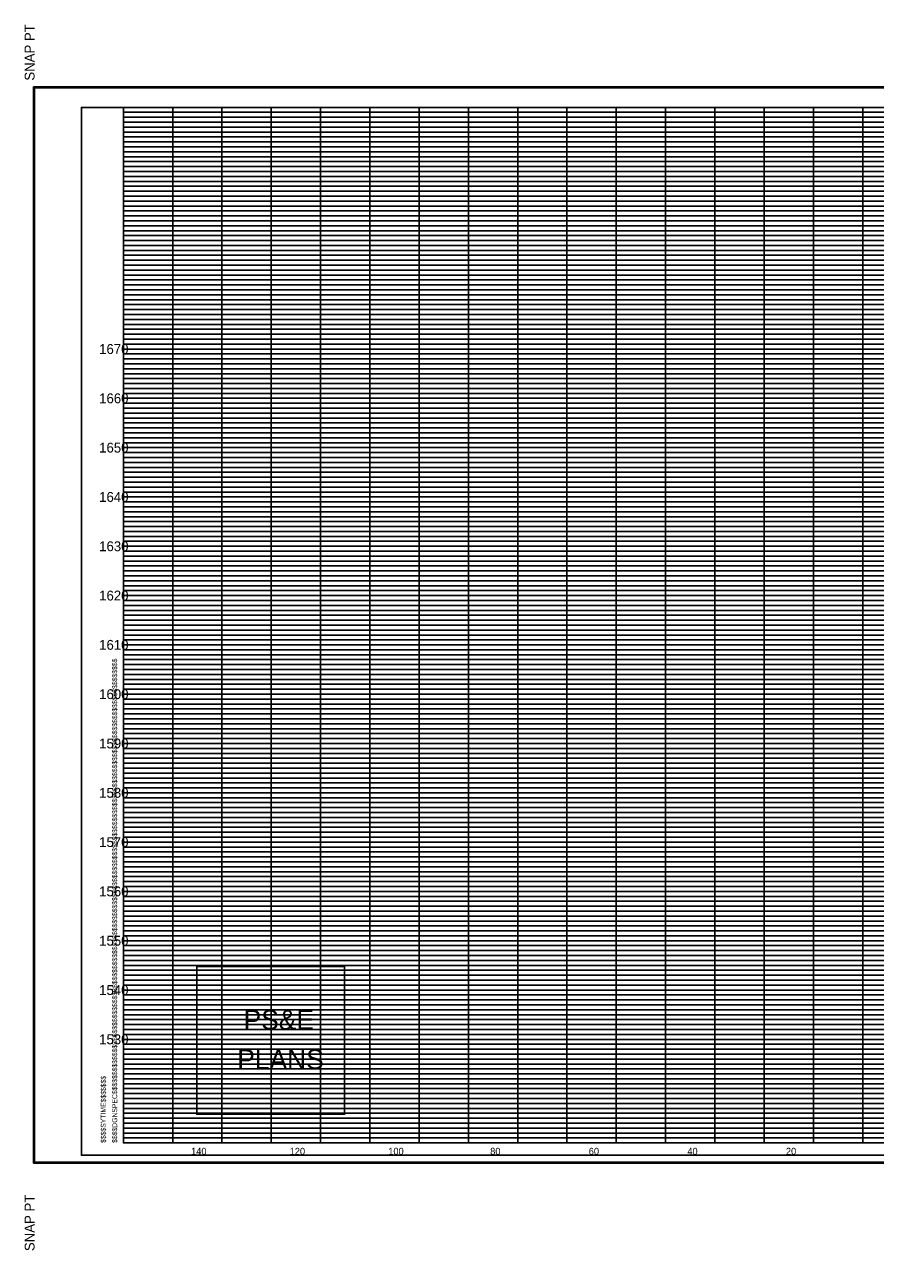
# Model space of a CAD drawing. Extents: x 980 to 1380, y 1248 to 3387.
# Drawn here: x 979.9 to 1152.6, y 2328.2 to 2576.8 of the extents above; entities that cross this region are included whole.
import ezdxf

# ---------------------------------------------------------------- set-up
doc = ezdxf.new("R2010")
doc.units = 0
for name, color, linetype in [('DESIGN - SHEET - Corner Text', 7, 'Continuous'), ('DESIGN - SHEET - Light Grid', 7, 'Continuous'), ('DESIGN - SHEET - Linework', 7, 'Continuous'), ('DESIGN - SHEET - Plot Shape', 7, 'Continuous'), ('DESIGN - TYPICAL - Text', 7, 'Continuous')]:
    doc.layers.add(name, color=color, linetype=linetype)

# ---------------------------------------------------------------- blocks, each defined once
blk = doc.blocks.new('XSTSHT')
at = {"layer": 'DESIGN - SHEET - Light Grid'}
for p, q in [((0, 20.9), (8, 20.9)), ((8, 20.9), (16, 20.9)), ((0, 20.8), (8, 20.8)), ((0, 20.7), (8, 20.7)), ((8, 20.8), (16, 20.8)), ((8, 20.7), (16, 20.7)), ((0, 20.6), (8, 20.6)), ((0, 20.5), (8, 20.5)), ((0, 20.4), (8, 20.4)), ((8, 20.6), (16, 20.6)), ((8, 20.5), (16, 20.5)), ((8, 20.4), (16, 20.4)), ((0, 20.3), (8, 20.3)), ((0, 20.2), (8, 20.2)), ((8, 20.3), (16, 20.3)), ((8, 20.2), (16, 20.2)), ((0, 20.1), (8, 20.1)), ((0, 19.9), (8, 19.9)), ((8, 20.1), (16, 20.1)), ((8, 19.9), (16, 19.9)), ((0, 19.8), (8, 19.8)), ((0, 19.7), (8, 19.7)), ((8, 19.8), (16, 19.8)), ((8, 19.7), (16, 19.7)), ((0, 19.6), (8, 19.6)), ((0, 19.5), (8, 19.5)), ((0, 19.4), (8, 19.4)), ((8, 19.6), (16, 19.6)), ((8, 19.5), (16, 19.5)), ((8, 19.4), (16, 19.4)), ((0, 19.3), (8, 19.3)), ((0, 19.2), (8, 19.2)), ((8, 19.3), (16, 19.3)), ((8, 19.2), (16, 19.2)), ((0, 19.1), (8, 19.1)), ((0, 18.9), (8, 18.9)), ((8, 19.1), (16, 19.1)), ((8, 18.9), (16, 18.9)), ((0, 18.8), (8, 18.8)), ((0, 18.7), (8, 18.7)), ((8, 18.8), (16, 18.8)), ((8, 18.7), (16, 18.7)), ((0, 18.6), (8, 18.6)), ((0, 18.5), (8, 18.5)), ((0, 18.4), (8, 18.4)), ((8, 18.6), (16, 18.6)), ((8, 18.5), (16, 18.5)), ((8, 18.4), (16, 18.4)), ((0, 18.3), (8, 18.3)), ((0, 18.2), (8, 18.2)), ((8, 18.3), (16, 18.3)), ((8, 18.2), (16, 18.2)), ((0, 18.1), (8, 18.1)), ((8, 18.1), (16, 18.1)), ((0, 17.9), (8, 17.9)), ((0, 17.8), (8, 17.8)), ((0, 17.7), (8, 17.7)), ((8, 17.9), (16, 17.9)), ((8, 17.8), (16, 17.8)), ((8, 17.7), (16, 17.7)), ((0, 17.6), (8, 17.6)), ((0, 17.5), (8, 17.5)), ((8, 17.6), (16, 17.6)), ((8, 17.5), (16, 17.5)), ((0, 17.4), (8, 17.4)), ((0, 17.3), (8, 17.3)), ((0, 17.2), (8, 17.2)), ((8, 17.4), (16, 17.4)), ((8, 17.3), (16, 17.3)), ((8, 17.2), (16, 17.2)), ((0, 17.1), (8, 17.1)), ((8, 17.1), (16, 17.1)), ((0, 16.9), (8, 16.9)), ((0, 16.8), (8, 16.8)), ((0, 16.7), (8, 16.7)), ((8, 16.9), (16, 16.9)), ((8, 16.8), (16, 16.8)), ((8, 16.7), (16, 16.7)), ((0, 16.6), (8, 16.6)), ((0, 16.5), (8, 16.5)), ((8, 16.6), (16, 16.6)), ((8, 16.5), (16, 16.5)), ((0, 16.4), (8, 16.4)), ((0, 16.3), (8, 16.3)), ((0, 16.2), (8, 16.2)), ((8, 16.4), (16, 16.4)), ((8, 16.3), (16, 16.3)), ((8, 16.2), (16, 16.2)), ((0, 16.1), (8, 16.1)), ((8, 16.1), (16, 16.1)), ((0, 15.9), (8, 15.9)), ((0, 15.8), (8, 15.8)), ((0, 15.7), (8, 15.7)), ((8, 15.9), (16, 15.9)), ((8, 15.8), (16, 15.8)), ((8, 15.7), (16, 15.7)), ((0, 15.6), (8, 15.6)), ((0, 15.5), (8, 15.5)), ((8, 15.6), (16, 15.6)), ((8, 15.5), (16, 15.5)), ((0, 15.4), (8, 15.4)), ((0, 15.3), (8, 15.3)), ((0, 15.2), (8, 15.2)), ((8, 15.4), (16, 15.4)), ((8, 15.3), (16, 15.3)), ((8, 15.2), (16, 15.2)), ((0, 15.1), (8, 15.1)), ((8, 15.1), (16, 15.1)), ((0, 14.9), (8, 14.9)), ((0, 14.8), (8, 14.8)), ((0, 14.7), (8, 14.7)), ((8, 14.9), (16, 14.9)), ((8, 14.8), (16, 14.8)), ((8, 14.7), (16, 14.7)), ((0, 14.6), (8, 14.6)), ((0, 14.5), (8, 14.5)), ((8, 14.6), (16, 14.6)), ((8, 14.5), (16, 14.5)), ((0, 14.4), (8, 14.4)), ((0, 14.3), (8, 14.3)), ((0, 14.2), (8, 14.2)), ((8, 14.4), (16, 14.4)), ((8, 14.3), (16, 14.3)), ((8, 14.2), (16, 14.2)), ((0, 14.1), (8, 14.1)), ((8, 14.1), (16, 14.1)), ((0, 13.9), (8, 13.9)), ((0, 13.8), (8, 13.8)), ((0, 13.7), (8, 13.7)), ((8, 13.9), (16, 13.9)), ((8, 13.8), (16, 13.8)), ((8, 13.7), (16, 13.7)), ((0, 13.6), (8, 13.6)), ((0, 13.5), (8, 13.5)), ((8, 13.6), (16, 13.6)), ((8, 13.5), (16, 13.5)), ((0, 13.4), (8, 13.4)), ((0, 13.3), (8, 13.3)), ((0, 13.2), (8, 13.2)), ((8, 13.4), (16, 13.4)), ((8, 13.3), (16, 13.3)), ((8, 13.2), (16, 13.2)), ((0, 13.1), (8, 13.1)), ((8, 13.1), (16, 13.1)), ((0, 12.9), (8, 12.9)), ((0, 12.8), (8, 12.8)), ((0, 12.7), (8, 12.7)), ((8, 12.9), (16, 12.9)), ((8, 12.8), (16, 12.8)), ((8, 12.7), (16, 12.7)), ((0, 12.6), (8, 12.6)), ((0, 12.5), (8, 12.5)), ((8, 12.6), (16, 12.6)), ((8, 12.5), (16, 12.5)), ((0, 12.4), (8, 12.4)), ((0, 12.3), (8, 12.3)), ((0, 12.2), (8, 12.2)), ((8, 12.4), (16, 12.4)), ((8, 12.3), (16, 12.3)), ((8, 12.2), (16, 12.2)), ((0, 12.1), (8, 12.1)), ((8, 12.1), (16, 12.1)), ((0, 11.9), (8, 11.9)), ((0, 11.8), (8, 11.8)), ((0, 11.7), (8, 11.7)), ((8, 11.9), (16, 11.9)), ((8, 11.8), (16, 11.8)), ((8, 11.7), (16, 11.7)), ((0, 11.6), (8, 11.6)), ((0, 11.5), (8, 11.5)), ((8, 11.6), (16, 11.6)), ((8, 11.5), (16, 11.5)), ((0, 11.4), (8, 11.4)), ((0, 11.3), (8, 11.3)), ((0, 11.2), (8, 11.2)), ((8, 11.4), (16, 11.4)), ((8, 11.3), (16, 11.3)), ((8, 11.2), (16, 11.2)), ((0, 11.1), (8, 11.1)), ((8, 11.1), (16, 11.1)), ((0, 10.9), (8, 10.9)), ((0, 10.8), (8, 10.8)), ((0, 10.7), (8, 10.7)), ((8, 10.9), (16, 10.9)), ((8, 10.8), (16, 10.8)), ((8, 10.7), (16, 10.7)), ((0, 10.6), (8, 10.6)), ((0, 10.5), (8, 10.5)), ((8, 10.6), (16, 10.6)), ((8, 10.5), (16, 10.5)), ((0, 10.4), (8, 10.4)), ((0, 10.3), (8, 10.3)), ((0, 10.2), (8, 10.2)), ((8, 10.4), (16, 10.4)), ((8, 10.3), (16, 10.3)), ((8, 10.2), (16, 10.2)), ((0, 10.1), (8, 10.1)), ((8, 10.1), (16, 10.1)), ((0, 9.9), (8, 9.9)), ((0, 9.8), (8, 9.8)), ((0, 9.7), (8, 9.7)), ((8, 9.9), (16, 9.9)), ((8, 9.8), (16, 9.8)), ((8, 9.7), (16, 9.7)), ((0, 9.6), (8, 9.6)), ((0, 9.5), (8, 9.5)), ((8, 9.6), (16, 9.6)), ((8, 9.5), (16, 9.5)), ((0, 9.4), (8, 9.4)), ((0, 9.3), (8, 9.3)), ((0, 9.2), (8, 9.2)), ((8, 9.4), (16, 9.4)), ((8, 9.3), (16, 9.3)), ((8, 9.2), (16, 9.2)), ((0, 9.1), (8, 9.1)), ((8, 9.1), (16, 9.1)), ((0, 8.9), (8, 8.9)), ((0, 8.8), (8, 8.8)), ((8, 8.9), (16, 8.9)), ((8, 8.8), (16, 8.8)), ((0, 8.7), (8, 8.7)), ((0, 8.6), (8, 8.6)), ((0, 8.5), (8, 8.5)), ((8, 8.7), (16, 8.7)), ((8, 8.6), (16, 8.6)), ((8, 8.5), (16, 8.5)), ((0, 8.4), (8, 8.4)), ((0, 8.3), (8, 8.3)), ((8, 8.4), (16, 8.4)), ((8, 8.3), (16, 8.3)), ((0, 8.2), (8, 8.2)), ((0, 8.1), (8, 8.1)), ((8, 8.2), (16, 8.2)), ((8, 8.1), (16, 8.1)), ((0, 7.9), (8, 7.9)), ((0, 7.8), (8, 7.8)), ((8, 7.9), (16, 7.9)), ((8, 7.8), (16, 7.8)), ((0, 7.7), (8, 7.7)), ((0, 7.6), (8, 7.6)), ((0, 7.5), (8, 7.5)), ((8, 7.7), (16, 7.7)), ((8, 7.6), (16, 7.6)), ((8, 7.5), (16, 7.5)), ((0, 7.4), (8, 7.4)), ((0, 7.3), (8, 7.3)), ((8, 7.4), (16, 7.4)), ((8, 7.3), (16, 7.3)), ((0, 7.2), (8, 7.2)), ((0, 7.1), (8, 7.1)), ((8, 7.2), (16, 7.2)), ((8, 7.1), (16, 7.1)), ((0, 6.9), (8, 6.9)), ((0, 6.8), (8, 6.8)), ((8, 6.9), (16, 6.9)), ((8, 6.8), (16, 6.8)), ((0, 6.7), (8, 6.7)), ((0, 6.6), (8, 6.6)), ((0, 6.5), (8, 6.5)), ((8, 6.7), (16, 6.7)), ((8, 6.6), (16, 6.6)), ((8, 6.5), (16, 6.5)), ((0, 6.4), (8, 6.4)), ((0, 6.3), (8, 6.3)), ((8, 6.4), (16, 6.4)), ((8, 6.3), (16, 6.3)), ((0, 6.2), (8, 6.2)), ((0, 6.1), (8, 6.1)), ((8, 6.2), (16, 6.2)), ((8, 6.1), (16, 6.1)), ((0, 5.9), (8, 5.9)), ((0, 5.8), (8, 5.8)), ((8, 5.9), (16, 5.9)), ((8, 5.8), (16, 5.8)), ((0, 5.7), (8, 5.7)), ((0, 5.6), (8, 5.6)), ((0, 5.5), (8, 5.5)), ((8, 5.7), (16, 5.7)), ((8, 5.6), (16, 5.6)), ((8, 5.5), (16, 5.5)), ((0, 5.4), (8, 5.4)), ((0, 5.3), (8, 5.3)), ((8, 5.4), (16, 5.4)), ((8, 5.3), (16, 5.3)), ((0, 5.2), (8, 5.2)), ((0, 5.1), (8, 5.1)), ((8, 5.2), (16, 5.2)), ((8, 5.1), (16, 5.1)), ((0, 4.9), (8, 4.9)), ((0, 4.8), (8, 4.8)), ((8, 4.9), (16, 4.9)), ((8, 4.8), (16, 4.8)), ((0, 4.7), (8, 4.7)), ((0, 4.6), (8, 4.6)), ((0, 4.5), (8, 4.5)), ((8, 4.7), (16, 4.7)), ((8, 4.6), (16, 4.6)), ((8, 4.5), (16, 4.5)), ((0, 4.4), (8, 4.4)), ((0, 4.3), (8, 4.3)), ((8, 4.4), (16, 4.4)), ((8, 4.3), (16, 4.3)), ((0, 4.2), (8, 4.2)), ((0, 4.1), (8, 4.1)), ((8, 4.2), (16, 4.2)), ((8, 4.1), (16, 4.1)), ((0, 3.9), (8, 3.9)), ((0, 3.8), (8, 3.8)), ((8, 3.9), (16, 3.9)), ((8, 3.8), (16, 3.8)), ((0, 3.7), (8, 3.7)), ((0, 3.6), (8, 3.6)), ((0, 3.5), (8, 3.5)), ((8, 3.7), (16, 3.7)), ((8, 3.6), (16, 3.6)), ((8, 3.5), (16, 3.5)), ((0, 3.4), (8, 3.4)), ((0, 3.3), (8, 3.3)), ((8, 3.4), (16, 3.4)), ((8, 3.3), (16, 3.3)), ((0, 3.2), (8, 3.2)), ((0, 3.1), (8, 3.1)), ((8, 3.2), (16, 3.2)), ((8, 3.1), (16, 3.1)), ((0, 2.9), (8, 2.9)), ((0, 2.8), (8, 2.8)), ((8, 2.9), (16, 2.9)), ((8, 2.8), (16, 2.8)), ((0, 2.7), (8, 2.7)), ((0, 2.6), (8, 2.6)), ((0, 2.5), (8, 2.5)), ((8, 2.7), (16, 2.7)), ((8, 2.6), (16, 2.6)), ((8, 2.5), (16, 2.5)), ((0, 2.4), (8, 2.4)), ((0, 2.3), (8, 2.3)), ((8, 2.4), (16, 2.4)), ((8, 2.3), (16, 2.3)), ((0, 2.2), (8, 2.2)), ((0, 2.1), (8, 2.1)), ((8, 2.2), (16, 2.2)), ((8, 2.1), (16, 2.1)), ((0, 1.9), (8, 1.9)), ((0, 1.8), (8, 1.8)), ((8, 1.9), (16, 1.9)), ((8, 1.8), (16, 1.8)), ((0, 1.7), (8, 1.7)), ((0, 1.6), (8, 1.6)), ((0, 1.5), (8, 1.5)), ((8, 1.7), (16, 1.7)), ((8, 1.6), (16, 1.6)), ((8, 1.5), (16, 1.5)), ((0, 1.4), (8, 1.4)), ((0, 1.3), (8, 1.3)), ((8, 1.4), (16, 1.4)), ((8, 1.3), (16, 1.3)), ((0, 1.2), (8, 1.2)), ((0, 1.1), (8, 1.1)), ((8, 1.2), (16, 1.2)), ((8, 1.1), (16, 1.1)), ((0, 0.9), (8, 0.9)), ((0, 0.8), (8, 0.8)), ((8, 0.9), (16, 0.9)), ((8, 0.8), (16, 0.8)), ((0, 0.7), (8, 0.7)), ((0, 0.6), (8, 0.6)), ((0, 0.5), (8, 0.5)), ((8, 0.7), (16, 0.7)), ((8, 0.6), (16, 0.6)), ((8, 0.5), (16, 0.5)), ((0, 0.4), (8, 0.4)), ((0, 0.3), (8, 0.3)), ((8, 0.4), (16, 0.4)), ((8, 0.3), (16, 0.3)), ((0, 0.2), (8, 0.2)), ((0, 0.1), (8, 0.1)), ((8, 0.2), (16, 0.2)), ((8, 0.1), (16, 0.1))]:
    blk.add_line(p, q, dxfattribs=at)
at = {"layer": 'DESIGN - SHEET - Linework'}
for p, q in [((-1.823, -0.414), (-1.823, 21.414)), ((-1.823, 21.414), (32.217, 21.414)), ((1, 0), (1, 21)), ((2, 0), (2, 21)), ((3, 0), (3, 21)), ((4, 0), (4, 21)), ((5, 0), (5, 21)), ((6, 0), (6, 21)), ((7, 0), (7, 21)), ((8, 0), (8, 21)), ((9, 0), (9, 21)), ((10, 0), (10, 21)), ((11, 0), (11, 21)), ((12, 0), (12, 21)), ((13, 0), (13, 21)), ((14, 0), (14, 21)), ((15, 0), (15, 21)), ((0, 20), (28, 20)), ((0, 19), (32, 19)), ((0, 18), (32, 18)), ((0, 17), (32, 17)), ((0, 16), (32, 16)), ((0, 15), (32, 15)), ((0, 14), (32, 14)), ((0, 13), (32, 13)), ((0, 12), (32, 12)), ((0, 11), (32, 11)), ((0, 10), (32, 10)), ((0, 9), (32, 9)), ((0, 8), (32, 8)), ((0, 7), (32, 7)), ((0, 6), (32, 6)), ((0, 5), (32, 5)), ((0, 4), (32, 4)), ((0, 3), (32, 3)), ((0, 2), (32, 2)), ((0, 1), (32, 1)), ((-1.823, -0.414), (32.217, -0.414))]:
    blk.add_line(p, q, dxfattribs=at)
blk.add_lwpolyline([(0, 21), (0, 0), (32, 0), (32, 21), (0, 21)], dxfattribs=at)
at = {"layer": 'DESIGN - SHEET - Plot Shape'}
for points in [[(-1.803, 21.394), (32.197, 21.394), (32.197, -0.394), (-1.803, -0.394)], [(-0.85, 21), (32, 21), (32, -0.25), (-0.85, -0.25)]]:
    blk.add_lwpolyline(points, close=True, dxfattribs=at)
at = {"layer": 'DESIGN - SHEET - Corner Text'}
for s, height, p in [('  SNAP PT', 0.2, (-1.803, 21.394)), ('$$$$DGNSPEC$$$$$$$$$$$$$$$$$$$$$$$$$$$$$$$$$$$$$$$$$$$$$$$$$$$$$$$$$$$$$$$$$$$$$$$$$$$$$$$$$$$$$$$$$$$$$$$$$$$$$$$$$$$$$$$$$$$', 0.100002, (-0.126, 0)), ('$$$$SYTIME$$$$$$$', 0.1, (-0.358, 0)), ('SNAP PT  ', 0.2, (-1.803, -2.194))]:
    blk.add_text(s, height=height, rotation=90, dxfattribs=at).set_placement(p)

msp = doc.modelspace()

# ---------------------------------------------------------------- linework, layer by layer
at = {"layer": 'DESIGN - SHEET - Corner Text'}
msp.add_lwpolyline([(1014.87, 2385.8), (1014.87, 2355.8), (1044.87, 2355.8), (1044.87, 2385.8)], close=True, dxfattribs=at)
at = {"layer": 'DESIGN - SHEET - Plot Shape'}
msp.add_lwpolyline([(991.5, 2347.5), (1320, 2347.5), (1320, 2560), (991.5, 2560)], close=True, dxfattribs=at)

# ---------------------------------------------------------------- block references
at = {"layer": 'DESIGN - TYPICAL - Text', "xscale": 10, "yscale": 10}
msp.add_blockref('XSTSHT', (1000, 2350), dxfattribs=at)

# ---------------------------------------------------------------- texts
at = {"layer": 'DESIGN - SHEET - Corner Text'}
for s, p in [('PS&E', (1024.39, 2372.97)), ('PLANS', (1023.11, 2364.97))]:
    msp.add_text(s, height=4, dxfattribs=at).set_placement(p)
at = {"layer": 'DESIGN - TYPICAL - Text'}
for s, height, p in [('     1670     ', 2, (991.37, 2510)), ('     1660     ', 2, (991.37, 2500)), ('     1650     ', 2, (991.37, 2490)), ('     1640     ', 2, (991.37, 2480)), ('     1630     ', 2, (991.37, 2470)), ('     1620     ', 2, (991.37, 2460)), ('     1610     ', 2, (991.37, 2450)), ('     1600     ', 2, (991.37, 2440)), ('     1590     ', 2, (991.37, 2430)), ('     1580     ', 2, (991.37, 2420)), ('     1570     ', 2, (991.37, 2410)), ('     1560     ', 2, (991.37, 2400)), ('     1550     ', 2, (991.37, 2390)), ('     1540     ', 2, (991.37, 2380)), ('     1530     ', 2, (991.37, 2370)), ('     140     ', 1.4, (1011.14, 2347.6)), ('     120     ', 1.4, (1031.14, 2347.6)), ('     100     ', 1.4, (1051.14, 2347.6)), ('     80     ', 1.4, (1071.82, 2347.6)), ('     60     ', 1.4, (1091.82, 2347.6)), ('     40     ', 1.4, (1111.82, 2347.6)), ('     20     ', 1.4, (1131.82, 2347.6))]:
    msp.add_text(s, height=height, dxfattribs=at).set_placement(p)

doc.saveas('drawing.dxf')
